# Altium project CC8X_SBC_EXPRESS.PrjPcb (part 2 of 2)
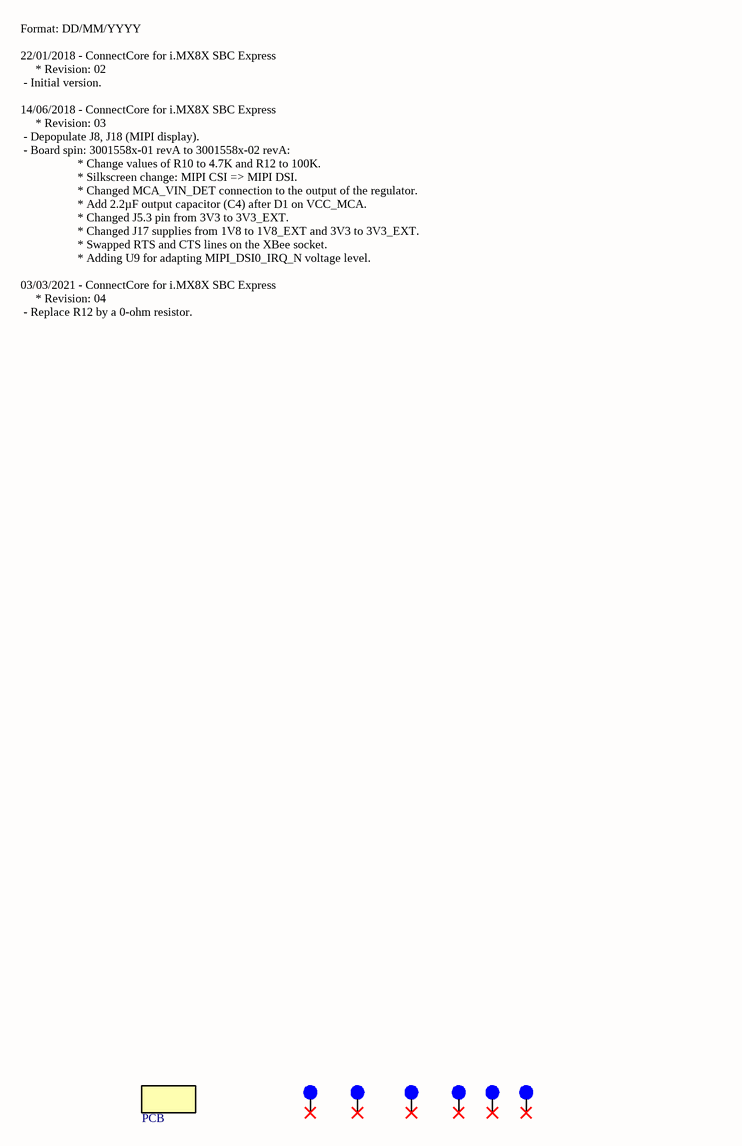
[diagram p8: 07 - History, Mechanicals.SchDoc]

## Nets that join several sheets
1V8_EXT: 02 - CC8X Module (R77.1), 05 - USB Host-Device, Raspberry PI expansion, User LED and button, XBee (J17.1 J17.5)
3V3_EXT: 02 - CC8X Module (J14.2 R1.1), 03 - Power, boot mode, reset, console, microSD, SWD, Coin Cell (11 pins), 04 - 10-100 Mb Ethernet, LVDS, MIPI (11 pins), 05 - USB Host-Device, Raspberry PI expansion, User LED and button, XBee (7 pins)
GND: 02 - CC8X Module (19 pins), 03 - Power, boot mode, reset, console, microSD, SWD, Coin Cell (27 pins), 04 - 10-100 Mb Ethernet, LVDS, MIPI (34 pins), 05 - USB Host-Device, Raspberry PI expansion, User LED and button, XBee (39 pins)
SHLD: 04 - 10-100 Mb Ethernet, LVDS, MIPI (J6.8 J6.SHLD1 J6.SHLD2 R42.2), 05 - USB Host-Device, Raspberry PI expansion, User LED and button, XBee (J9.SH1 J9.SH2 J9.SH3 J9.SH4)
VCC_MCA: 02 - CC8X Module (J1.59), 03 - Power, boot mode, reset, console, microSD, SWD, Coin Cell (8 pins), 05 - USB Host-Device, Raspberry PI expansion, User LED and button, XBee (J17.10)
VCC_SCU_1V8: 02 - CC8X Module (R3.2), 03 - Power, boot mode, reset, console, microSD, SWD, Coin Cell (R10.2 R13.2), 05 - USB Host-Device, Raspberry PI expansion, User LED and button, XBee (C7.2 U2.7 U2.10)
VIN: 02 - CC8X Module (J15.1 R2.1), 03 - Power, boot mode, reset, console, microSD, SWD, Coin Cell (6 pins), 04 - 10-100 Mb Ethernet, LVDS, MIPI (5 pins), 05 - USB Host-Device, Raspberry PI expansion, User LED and button, XBee (10 pins)
ADC_IN0: 02 - CC8X Module (J1.83), 05 - USB Host-Device, Raspberry PI expansion, User LED and button, XBee (J17.2)
ADC_IN1: 02 - CC8X Module (J1.82), 05 - USB Host-Device, Raspberry PI expansion, User LED and button, XBee (J17.3)
CONSOLE_RX: 02 - CC8X Module (J1.75), 03 - Power, boot mode, reset, console, microSD, SWD, Coin Cell (D2.2 J5.2)
CONSOLE_TX: 02 - CC8X Module (J1.74), 03 - Power, boot mode, reset, console, microSD, SWD, Coin Cell (D3.2 J5.1)
ENET0_CLK: 02 - CC8X Module (J1.96), 04 - 10-100 Mb Ethernet, LVDS, MIPI (U3.5)
ENET0_INT#: 02 - CC8X Module (J1.101), 04 - 10-100 Mb Ethernet, LVDS, MIPI (R25.1 U3.14)
ENET0_MDC: 02 - CC8X Module (J1.110), 04 - 10-100 Mb Ethernet, LVDS, MIPI (R23.1 U3.13)
ENET0_MDIO: 02 - CC8X Module (J1.109), 04 - 10-100 Mb Ethernet, LVDS, MIPI (R22.2 U3.12)
ENET0_PWR: 02 - CC8X Module (J1.107), 04 - 10-100 Mb Ethernet, LVDS, MIPI (Q1.G R73.1)
ENET0_RESET: 02 - CC8X Module (J1.100), 04 - 10-100 Mb Ethernet, LVDS, MIPI (R24.1 U3.15)
ENET0_RX_CTL: 02 - CC8X Module (J1.103), 04 - 10-100 Mb Ethernet, LVDS, MIPI (R27.2 R31.1 U3.11)
ENET0_RX_ER: 02 - CC8X Module (J1.106), 04 - 10-100 Mb Ethernet, LVDS, MIPI (R26.2 R30.1 U3.10)
ENET0_RXD0: 02 - CC8X Module (J1.104), 04 - 10-100 Mb Ethernet, LVDS, MIPI (R28.2 R32.1 U3.8)
ENET0_RXD1: 02 - CC8X Module (J1.105), 04 - 10-100 Mb Ethernet, LVDS, MIPI (R29.2 R33.1 U3.7)
ENET0_TX_CTL: 02 - CC8X Module (J1.97), 04 - 10-100 Mb Ethernet, LVDS, MIPI (U3.16)
ENET0_TXD0: 02 - CC8X Module (J1.98), 04 - 10-100 Mb Ethernet, LVDS, MIPI (U3.17)
ENET0_TXD1: 02 - CC8X Module (J1.99), 04 - 10-100 Mb Ethernet, LVDS, MIPI (U3.18)
GPIO1_17: 02 - CC8X Module (J1.78), 05 - USB Host-Device, Raspberry PI expansion, User LED and button, XBee (J11.7)
GPIO1_18: 02 - CC8X Module (J1.79), 05 - USB Host-Device, Raspberry PI expansion, User LED and button, XBee (J11.11)
GPIO1_19: 02 - CC8X Module (J1.76), 05 - USB Host-Device, Raspberry PI expansion, User LED and button, XBee (J11.40)
GPIO1_20: 02 - CC8X Module (J1.77), 05 - USB Host-Device, Raspberry PI expansion, User LED and button, XBee (J11.13)
GPIO1_28: 02 - CC8X Module (J1.20), 05 - USB Host-Device, Raspberry PI expansion, User LED and button, XBee (J11.15)
GPIO1_29: 02 - CC8X Module (J1.21), 05 - USB Host-Device, Raspberry PI expansion, User LED and button, XBee (J11.16)
GPIO1_30: 02 - CC8X Module (J1.22), 05 - USB Host-Device, Raspberry PI expansion, User LED and button, XBee (J11.18)
GPIO3_15: 02 - CC8X Module (J1.25), 05 - USB Host-Device, Raspberry PI expansion, User LED and button, XBee (J11.22)
GPIO4_20: 02 - CC8X Module (J1.2), 05 - USB Host-Device, Raspberry PI expansion, User LED and button, XBee (J11.26)
GPIO4_21: 02 - CC8X Module (J1.3), 05 - USB Host-Device, Raspberry PI expansion, User LED and button, XBee (J11.29)
GPIO4_22: 02 - CC8X Module (J1.4), 05 - USB Host-Device, Raspberry PI expansion, User LED and button, XBee (J11.31)
GPIO5_03: 02 - CC8X Module (J1.102), 05 - USB Host-Device, Raspberry PI expansion, User LED and button, XBee (J11.32)
I2C2_SCL: 02 - CC8X Module (J1.23), 05 - USB Host-Device, Raspberry PI expansion, User LED and button, XBee (J11.5)
I2C2_SDA: 02 - CC8X Module (J1.24), 05 - USB Host-Device, Raspberry PI expansion, User LED and button, XBee (J11.3)
I2C3_SCL: 02 - CC8X Module (J1.89), 05 - USB Host-Device, Raspberry PI expansion, User LED and button, XBee (J11.28)
I2C3_SDA: 02 - CC8X Module (J1.88), 05 - USB Host-Device, Raspberry PI expansion, User LED and button, XBee (J11.27)
MCA_IO1: 02 - CC8X Module (J1.52), 05 - USB Host-Device, Raspberry PI expansion, User LED and button, XBee (J17.6)
MCA_IO2: 02 - CC8X Module (J1.53), 05 - USB Host-Device, Raspberry PI expansion, User LED and button, XBee (J17.7)
MCA_IO3: 02 - CC8X Module (J1.54), 05 - USB Host-Device, Raspberry PI expansion, User LED and button, XBee (J11.37)
MCA_IO4: 02 - CC8X Module (J1.61), 05 - USB Host-Device, Raspberry PI expansion, User LED and button, XBee (J11.38)
MCA_IO5: 02 - CC8X Module (J1.62), 05 - USB Host-Device, Raspberry PI expansion, User LED and button, XBee (J11.33)
MCA_IO6: 02 - CC8X Module (J1.63), 05 - USB Host-Device, Raspberry PI expansion, User LED and button, XBee (J11.12)
MCA_IO7: 02 - CC8X Module (J1.64), 05 - USB Host-Device, Raspberry PI expansion, User LED and button, XBee (J11.35)
MCA_IO8: 02 - CC8X Module (J1.65), 05 - USB Host-Device, Raspberry PI expansion, User LED and button, XBee (J11.36)
MCA_IO9: 02 - CC8X Module (J1.66), 05 - USB Host-Device, Raspberry PI expansion, User LED and button, XBee (J17.8)
MCA_IO10: 02 - CC8X Module (J1.67), 05 - USB Host-Device, Raspberry PI expansion, User LED and button, XBee (J17.9)
MCA_VIN_DET: 02 - CC8X Module (J1.58), 03 - Power, boot mode, reset, console, microSD, SWD, Coin Cell (R9.1)
MIPI_DSI0_CLK_N: 02 - CC8X Module (J1.37), 04 - 10-100 Mb Ethernet, LVDS, MIPI (J8.11 L5.1)
MIPI_DSI0_CLK_P: 02 - CC8X Module (J1.38), 04 - 10-100 Mb Ethernet, LVDS, MIPI (J8.10 L5.4)
MIPI_DSI0_DATA0_N: 02 - CC8X Module (J1.40), 04 - 10-100 Mb Ethernet, LVDS, MIPI (J8.8 L2.1)
MIPI_DSI0_DATA0_P: 02 - CC8X Module (J1.41), 04 - 10-100 Mb Ethernet, LVDS, MIPI (J8.7 L2.4)
MIPI_DSI0_DATA1_N: 02 - CC8X Module (J1.43), 04 - 10-100 Mb Ethernet, LVDS, MIPI (J8.14 L3.1)
MIPI_DSI0_DATA1_P: 02 - CC8X Module (J1.44), 04 - 10-100 Mb Ethernet, LVDS, MIPI (J8.13 L3.4)
MIPI_DSI0_DATA2_N: 02 - CC8X Module (J1.46), 04 - 10-100 Mb Ethernet, LVDS, MIPI (L4.1)
MIPI_DSI0_DATA2_P: 02 - CC8X Module (J1.47), 04 - 10-100 Mb Ethernet, LVDS, MIPI (L4.4)
MIPI_DSI0_DATA3_N: 02 - CC8X Module (J1.49), 04 - 10-100 Mb Ethernet, LVDS, MIPI (L6.1)
MIPI_DSI0_DATA3_P: 02 - CC8X Module (J1.50), 04 - 10-100 Mb Ethernet, LVDS, MIPI (L6.4)
MIPI_DSI0_I2C0_SCL: 02 - CC8X Module (J1.17), 04 - 10-100 Mb Ethernet, LVDS, MIPI (J7.17 J8.5 J18.4 R74.1)
MIPI_DSI0_I2C0_SDA: 02 - CC8X Module (J1.18), 04 - 10-100 Mb Ethernet, LVDS, MIPI (J7.18 J8.4 J18.3 R75.1)
MIPI_DSI0_IRQ_N: 02 - CC8X Module (J1.1), 04 - 10-100 Mb Ethernet, LVDS, MIPI (J18.2 U9.4)
MIPI_DSI0_PWM0_OUT: 02 - CC8X Module (J1.19), 04 - 10-100 Mb Ethernet, LVDS, MIPI (J7.16)
SCU_BOOT_MODE0: 02 - CC8X Module (J1.68), 03 - Power, boot mode, reset, console, microSD, SWD, Coin Cell (R11.2 S3.2)
SCU_BOOT_MODE1: 02 - CC8X Module (J1.69), 03 - Power, boot mode, reset, console, microSD, SWD, Coin Cell (R10.1 S3.1)
SD_CARD_DETECT: 02 - CC8X Module (J1.108), 03 - Power, boot mode, reset, console, microSD, SWD, Coin Cell (J3.9 J3.10 R70.1)
SPI3_CS0: 02 - CC8X Module (J1.93), 05 - USB Host-Device, Raspberry PI expansion, User LED and button, XBee (J11.24)
SPI3_SCK: 02 - CC8X Module (J1.90), 05 - USB Host-Device, Raspberry PI expansion, User LED and button, XBee (J11.23)
SPI3_SDI: 02 - CC8X Module (J1.92), 05 - USB Host-Device, Raspberry PI expansion, User LED and button, XBee (J11.21)
SPI3_SDO: 02 - CC8X Module (J1.91), 05 - USB Host-Device, Raspberry PI expansion, User LED and button, XBee (J11.19)
SWD_CLK/PWR_IO: 02 - CC8X Module (J1.55), 03 - Power, boot mode, reset, console, microSD, SWD, Coin Cell (5 pins), 05 - USB Host-Device, Raspberry PI expansion, User LED and button, XBee (J17.17)
SWD_DIO/MCA_IO21: 02 - CC8X Module (J1.57), 03 - Power, boot mode, reset, console, microSD, SWD, Coin Cell (J19.2 SWD.2)
SYS_RESET: 02 - CC8X Module (J1.56), 03 - Power, boot mode, reset, console, microSD, SWD, Coin Cell (5 pins), 05 - USB Host-Device, Raspberry PI expansion, User LED and button, XBee (J17.18)
UART3_RX: 02 - CC8X Module (J1.70), 05 - USB Host-Device, Raspberry PI expansion, User LED and button, XBee (U2.9)
UART3_TX: 02 - CC8X Module (J1.71), 05 - USB Host-Device, Raspberry PI expansion, User LED and button, XBee (U2.8)
USB_OTG1_ID: 02 - CC8X Module (J1.118), 05 - USB Host-Device, Raspberry PI expansion, User LED and button, XBee (R76.2)
USB_OTG1_N: 02 - CC8X Module (J1.114), 05 - USB Host-Device, Raspberry PI expansion, User LED and button, XBee (L10.4)
USB_OTG1_P: 02 - CC8X Module (J1.113), 05 - USB Host-Device, Raspberry PI expansion, User LED and button, XBee (L10.1)
USB_OTG2_N: 02 - CC8X Module (J1.112), 05 - USB Host-Device, Raspberry PI expansion, User LED and button, XBee (L11.4)
USB_OTG2_P: 02 - CC8X Module (J1.111), 05 - USB Host-Device, Raspberry PI expansion, User LED and button, XBee (L11.1)
USDHC1_CLK: 02 - CC8X Module (J1.10), 03 - Power, boot mode, reset, console, microSD, SWD, Coin Cell (R19.1)
USDHC1_CMD: 02 - CC8X Module (J1.5), 03 - Power, boot mode, reset, console, microSD, SWD, Coin Cell (J3.3 R14.1)
USDHC1_DATA0: 02 - CC8X Module (J1.6), 03 - Power, boot mode, reset, console, microSD, SWD, Coin Cell (J3.7 R18.1)
USDHC1_DATA1: 02 - CC8X Module (J1.7), 03 - Power, boot mode, reset, console, microSD, SWD, Coin Cell (J3.8 R17.1)
USDHC1_DATA2: 02 - CC8X Module (J1.8), 03 - Power, boot mode, reset, console, microSD, SWD, Coin Cell (J3.1 R16.1)
USDHC1_DATA3: 02 - CC8X Module (J1.9), 03 - Power, boot mode, reset, console, microSD, SWD, Coin Cell (J3.2 R15.1)
USER_BUTTON: 02 - CC8X Module (J1.86), 05 - USB Host-Device, Raspberry PI expansion, User LED and button, XBee (J17.15 R61.1)
USER_LED: 02 - CC8X Module (J1.87), 05 - USB Host-Device, Raspberry PI expansion, User LED and button, XBee (J17.14 R59.2)
XBEE_ON/SLP_N: 02 - CC8X Module (J1.36), 05 - USB Host-Device, Raspberry PI expansion, User LED and button, XBee (J13.8 J17.13)
XBEE_RESET_N: 02 - CC8X Module (J1.35), 05 - USB Host-Device, Raspberry PI expansion, User LED and button, XBee (J12.5 J17.11)
XBEE_SLEEP_RQ: 02 - CC8X Module (J1.26), 05 - USB Host-Device, Raspberry PI expansion, User LED and button, XBee (J12.9 J17.12 R54.2)
XBEE_UART_CTS: 02 - CC8X Module (J1.81), 05 - USB Host-Device, Raspberry PI expansion, User LED and button, XBee (J13.9)
XBEE_UART_RTS: 02 - CC8X Module (J1.80), 05 - USB Host-Device, Raspberry PI expansion, User LED and button, XBee (J13.5 R57.2)
XBEE_UART_RX: 02 - CC8X Module (J1.14), 05 - USB Host-Device, Raspberry PI expansion, User LED and button, XBee (R62.1 R67.2)
XBEE_UART_TX: 02 - CC8X Module (J1.13), 05 - USB Host-Device, Raspberry PI expansion, User LED and button, XBee (R63.1 R66.2)

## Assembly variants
55002011-01: not fitted C13 C14 C15 C16 C17 C26 J8 J14 J15 J16 J17 J18 J19 L16 R23 R26 R31 R32 R33 R50 R51 R52 R53 R54 R55 R56 R57 R58 R66 R67 R71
